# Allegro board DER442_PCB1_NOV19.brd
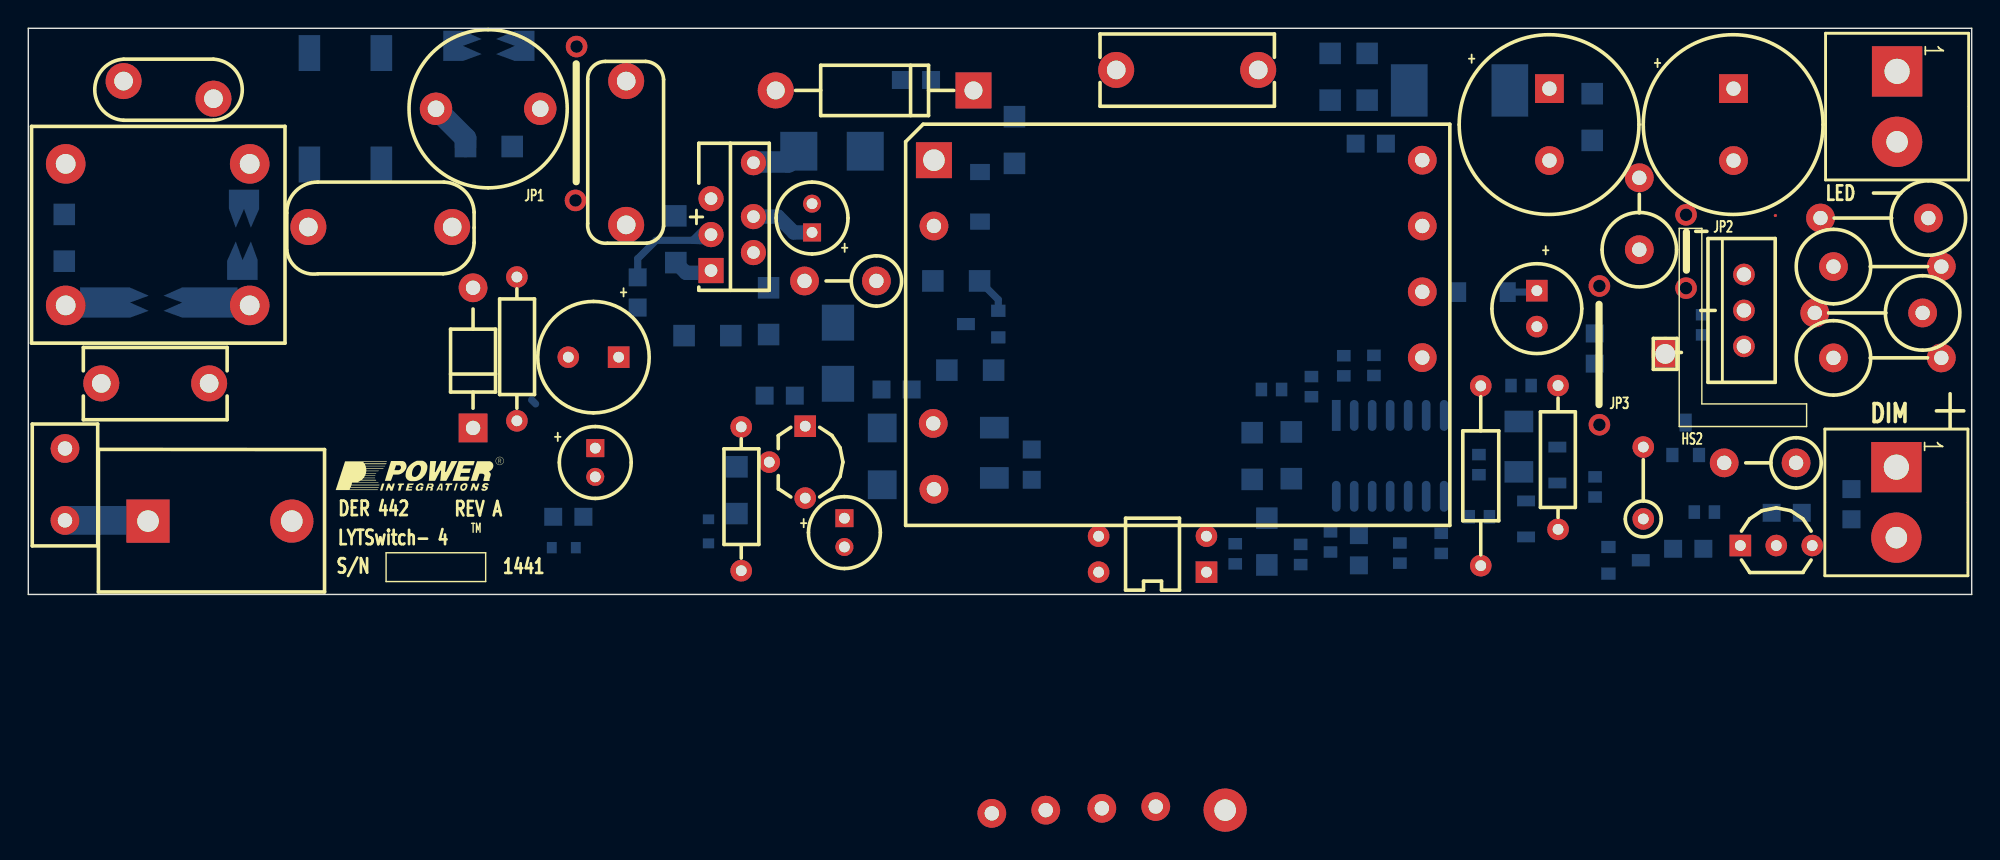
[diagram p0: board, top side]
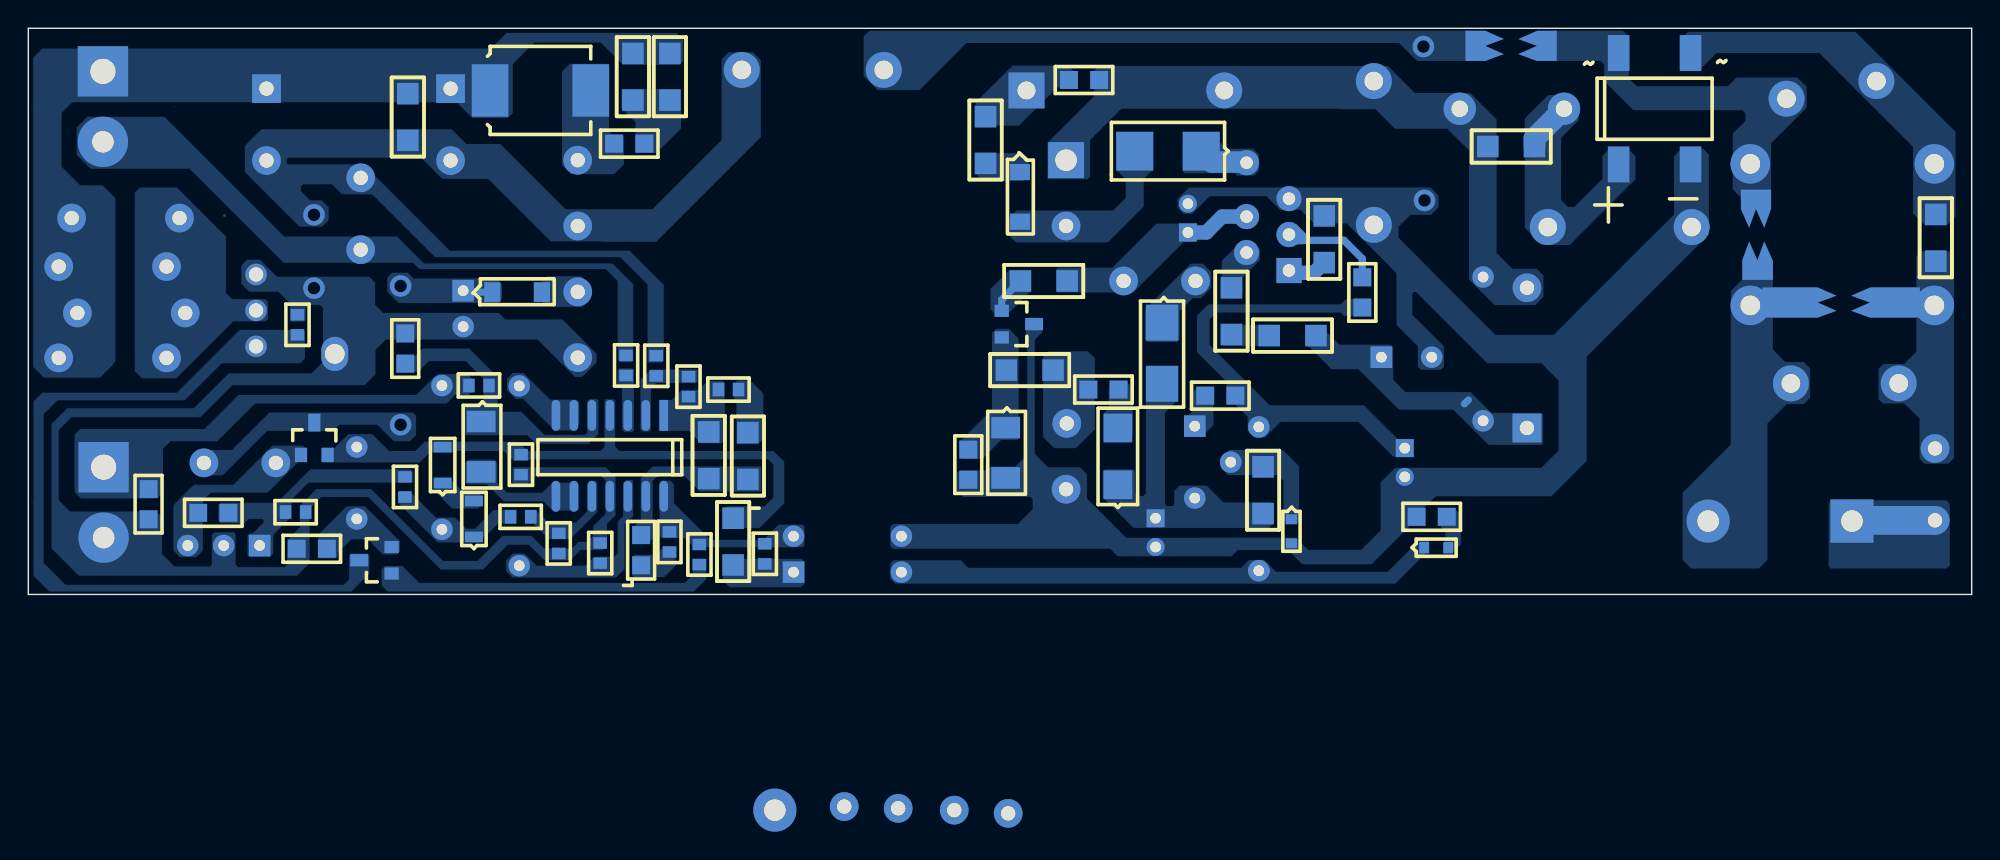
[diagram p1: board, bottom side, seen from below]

Outline 137.3 x 40 mm; copper layers: TOP, BOTTOM. Coordinates in mm from the lower left corner of the outline.
Outline path: 0,40 0,0 137.3,0 137.3,40 0,40

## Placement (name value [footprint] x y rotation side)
BR1  DF08S  [PISMDDFS]  24.94 30.43 0 bottom
C1  47 nF  [PI_NP395X200LS300D040]  5.16 14.91 0 top
C2  100 nF  [PINPCAPRAD500X260400040]  29.97 25.98 180 top
C3  220 nF  [PI_NP_CAP_RAD470X220LS400D40]  42.24 36.27 270 top
C4  4.7 uF  [PIPOLCAPCLYD320LS140030]  39.93 16.76 180 top
C5  1 nF  [PISMC0805]  61.65 36.35 0 bottom
C6  4.7 uF  [PIPOLCAPCLYD200LS80030]  55.37 25.58 90 top
C7  10 uF  [PIPOLCAPCLYD200LS80030]  40.06 10.34 270 top
C8  10 uF  [PIPOLCAPCLYD200LS80030]  57.66 5.38 270 top
C9  2.2nF  [PI_NP475X200LS395D040]  76.86 37.06 0 top
C15  1 uF  [PISMC0805]  125.3 5.77 180 bottom
C16  100 nF  [PISMC0603]  102.49 9.88 270 bottom
C17  10 uF  [PISMC0805]  94.01 2.06 90 bottom
C18  1 nF  [PISMC0805]  110.67 16.31 90 bottom
C21  100 uF  [PIPOLCAPCYLD250LS100030]  106.58 21.46 270 top
C24  330 uF  [PIPOLCAPCLYD500LS200040]  120.47 35.74 270 top
C25  330 uF  [PIPOLCAPCLYD500LS200040]  107.47 35.74 270 top
C26  Option  [PISMC1206]  86.46 11.43 270 bottom
C27  100 pF  [PISMC0805]  95.91 31.85 180 bottom
C28  10 uF  [PISMC0805]  128.8 5.31 90 bottom
D5  1N4007  [PIDV200X110X040DO41]  31.42 11.76 90 top
D6  UFM15PL-TP  [PI_SM_SOD-123_12]  67.23 29.84 270 bottom
D7  ES2D  [PISMDO214AA12]  54.43 31.32 0 bottom
D8  ES1B-13-F  [PISMDO214AC12]  57.2 19.2 270 bottom
D9  US1D  [PISMDSMA]  60.33 7.75 90 bottom
D10  DL4148  [PISMDMINIMELF]  68.25 11.79 270 bottom
D13  DL4148  [PISMDMINIMELF]  105.31 12.22 270 bottom
D16  ES3G-E3/57T  [PISMDO214AB12]  104.67 35.61 180 bottom
D17  DA22F2100L  [PI_SM_SOD-123_12]  104.52 21.36 180 bottom
D18  BAV16WS-7-F  [PISMSOD323]  108.03 7.87 90 bottom
D19  BAV16WS-7-F  [PISMSOD323]  105.82 4.06 90 bottom
F1  3.15 A  [PI_RST_MICROFUSE]  2.59 5.23 90 top
HS_POST1  Option  [PI_HSK_POST]  115.65 16.99 90 top
J1  TERMINAL BLOCK  [PI_TERM_BLOCK_3PIN]  8.46 5.18 270 top
J2  CON1  [PI_HDR_2PIN_PHOENIX_196LS]  132.03 36.96 270 top
J3  CON2  [PI_HDR_2PIN_PHOENIX_196LS]  131.98 8.99 270 top
L1  8.8 mH  [PIIND4P710X590LS512X055]  2.64 20.42 90 top
L4  1.5 mh  [PI_CHOKE_710HX450LS290D046]  28.8 34.32 0 top
NOREF  -  []  -168.95 52.63 0 top
NOREF#2  -  []  -246.76 -146.38 0 top
NOREF#3  -  []  0 40 0 top
NOREF#4  -  []  21.72 7.32 0 top
NOREF#5  -  []  0 0 90 top
Q1  2N5551  [PITO92R100]  54.89 11.89 270 top
Q2  MMBT3904  [PISMSOT23132]  116.15 9.86 180 bottom
Q5  MMBT3906  [PISMSOT23132]  111.63 3.35 90 bottom
Q6  2SC4883  [PI_TO220F]  121.21 17.53 90 top
R1  75 k  [PISMR1206]  2.54 23.55 90 bottom
R4  1 M  [PISMR1206]  46.33 18.29 0 bottom
R5  825 k  [PISMR1206]  52.3 18.36 90 bottom
R6  680 k  [PI14WVRESD100LS100D030#2]  34.52 22.43 270 top
R9  75  [PISMR1206]  69.67 33.76 270 bottom
R10  24.9 k  [PISMR1206]  45.75 23.44 90 bottom
R11  4.7 k  [PI1WRESD200LS725D040]  59.92 22.15 180 top
R12  7.5 k  [PISMR0805]  54.15 14.05 180 bottom
R13  8.2 k  [PISMR0805]  43.05 20.27 90 bottom
R17  5.1 k  [PISMR1206]  50.06 5.71 90 bottom
R18  3.3 k  [PI14WVRESD100LS100D030#2]  50.37 11.84 270 top
R19  20  [PISMR1206]  63.91 22.15 0 bottom
R20  1.74 k  [PISMR0805]  37.08 5.49 0 bottom
R21  78.7 k  [PISMR1206]  64.9 15.85 0 bottom
R22  5.49 k  [PISMR0805]  70.89 10.24 270 bottom
R25  4.32 k  [PISMR0603]  92.94 15.44 90 bottom
R26  4.32 k  [PISMR0603]  95.07 15.47 90 bottom
R28  88.7 k  [PISMR0603]  90.65 15.39 270 bottom
R29  1 k  [PI1WRESD200LS725D040]  124.89 9.3 180 top
R31  30.9 k  [PISMR0603]  110.69 6.88 90 bottom
R32  10 k  [PISMR0603]  119.13 5.82 180 bottom
R33  3.01 k  [PISMR1206]  87.5 5.38 270 bottom
R34  3.65 k  [PISMR0603]  92 4.42 270 bottom
R35  4.7 k  [PISMR1206]  89.23 8.18 90 bottom
R36  24 k  [PI14WVRESD100LS100D030#3]  102.62 14.73 270 top
R37  9.09 k  [PISMR0603]  96.9 2.21 90 bottom
R38  88.7 k  [PISMR0603]  103.23 5.49 180 bottom
R39  14.7 k  [PISMR0603]  99.82 4.32 270 bottom
R40  20 k  [PI14WVRESD100LS100D030#2]  108.08 4.6 90 top
R41  10 k  [PISMR0603]  104.75 14.76 0 bottom
R45  Option  [PISMR1206]  30.89 31.65 0 bottom
R46  0.25  [PI1WRESD200LS500D040]  113.82 24.36 90 top
R49  2 k  [PI14WVRESD100LS100D030]  114.1 5.33 90 top
R51  1.1 k  [PI2WRESD200LS725D040]  134.24 26.59 180 top
R56  1 k  [PISMR0603]  89.89 2.11 90 bottom
R58  1.1 k  [PI2WRESD200LS725D040]  133.83 19.89 180 top
R59  1.1 k  [PI2WRESD200LS725D040]  127.53 23.16 0 top
R60  1.1 k  [PI2WRESD200LS725D040]  127.53 16.71 0 top
R61  750  [PISMR0805]  118.34 3.23 180 bottom
R62  Option  [PISMR0603]  88.54 14.48 180 bottom
R66  Option  [PISMR0603]  85.27 2.16 90 bottom
R67  Option  [PISMR0603]  118.29 18.34 90 bottom
R68  20.0  [PISMR0805]  60.27 14.48 0 bottom
R69  392 k  [PISMR1206]  110.49 35.38 270 bottom
R70  82  [PISMR1206]  91.97 34.92 90 bottom
R71  82  [PISMR1206]  94.59 34.92 90 bottom
RV1  140 Vac  [PINPCAPRAD370X156250040]  6.73 36.3 0 top
T1  EF25  [PI_BOBBIN_EF25_H_12P]  63.98 30.68 0 top
U1  LYT4315E  [PIICESIP76TH]  48.23 22.89 90 top
U2  LM431AIM3  [PISMSOT23123]  68.53 18.16 270 bottom
U3  SFH615A--3  [PI_DIP4]  83.24 1.57 90 top
U5  LM431_A  [PI_TL431CLP]  120.95 3.45 0 top
U6  LM324M  [PISOG05014WB300L400]  92.41 12.65 0 bottom
VR1  P6KE150A  [PIDV200X140X050DO15DO204AC]  66.78 35.61 180 top
VR2  DZ2S08200L  [PI_SM_D_SSMINI2P]  48.06 5.31 270 bottom
VR3  DZ2S03900L  [PI_SM_D_SSMINI2P]  38.68 3.3 180 bottom

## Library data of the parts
BR1 = DIODE BRIDGE_+-~~
C1 C3 C9 C15-C18 C26-C28 = CAP NP
C2 = CAP NP: alternate symbols: (pinpcaprad500x260400040h)
C4 = CAP POL: alternate symbols: (pipolcapclyd320ls140030h); tolerance: 20
C5 = CAP NP: tolerance: 10
C6 = CAP POL: alternate symbols: (pipolcapclyd200ls80030h)
C7 = CAP POL
C8 = CAP POL: tolerance: 20
C21 = CAP POL: alternate symbols: (pipolcapcyld250ls100030h)
C24 C25 = CAP POL: alternate symbols: (pipolcapclyd500ls2000401000lh)
D5 = DIODE: alternate symbols: (pidax475x125040do41,pidv200x110x040do41wbead,pidax390x125040do41)
D6-D10 D13 D16-D19 = DIODE
F1 = FUSE
HS_POST1 = HS_POST
J1 = CON3
J2 J3 = CON2
L1 = INDUCTOR_4P_NP
L4 = INDUCTOR: tolerance: 0.1
Q1 = NPN_EBC: alternate symbols: (PIT092100)
Q2 = NPN_BEC
Q5 = PNP_BEC
Q6 = NPN_BCE: alternate symbols: (pi_to220F_vf1)
R1 R4 R5 R9 R10 R12 R13 R17 R20 R22 R28 R31-R34 R37-R39 R41 R56 R61 R62 R66-R71 = R
R6 R18 R36 R40 R49 = R: alternate symbols: (pi14wvresd100ls200d030,pi14wresd100ls400d030,pi14wresd100ls500d030)
R11 R29 = R: alternate symbols: (pi1wvresd120ls200d040,pi1wvresd120ls300d040,pi1wvresd200ls200d040,pi1wvresd200ls300d040,pi1wvresd200ls350d040)
R19 R21 R25 R26 R35 R45 = R: tolerance: 5%
R46 = R: alternate symbols: (pi1wvresd200ls200d040)
R51 R58-R60 = R: alternate symbols: (pi2wresd200ls900d040,pi2wvresd200ls300d040,pi2wvresd200ls400d040)
RV1 = VARISTOR
T1 = BEI30_12P/GENERIC
U1 = LNK40X_eSIP
U2 = TL431/SOT-23_CAR
U3 = OPTO_A_B
U5 = KA431A/TO92: tolerance: 1%
U6 = LM324
VR1 = DIODE_ZENER: alternate symbols: (pidax550x140050do15do204ac)
VR2 VR3 = DIODE_ZENER

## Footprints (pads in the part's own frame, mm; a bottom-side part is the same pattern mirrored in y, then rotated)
PI1WRESD200LS500D040
  round 2.032 hole 1.016: 1(0,0) 2(5.08,0)
PI1WRESD200LS725D040
  round 2.032 hole 1.016: 1(0,0) 2(5.08,0)
PI2WRESD200LS725D040
  round 2.032 hole 1.016: 1(0,0) 2(7.62,0)
PI14WVRESD100LS100D030
  round 1.524 hole 0.762: 1(0,0) 2(5.08,0)
PI14WVRESD100LS100D030#2
  round 1.524 hole 0.762: 1(0,0) 2(10.16,0)
PI14WVRESD100LS100D030#3
  round 1.524 hole 0.762: 1(0,0) 2(12.7,0)
PI_BOBBIN_EF25_H_12P
  rect 2.54x2.54 hole 1.524: 1(0,0)
  round 2.032 hole 1.016: 2(0,-4.651) 3(4.089,-46.152) 4(7.899,-45.923) 5(-0.051,-18.6) 6(0,-23.251) 7(11.862,-45.796) 8(15.672,-45.669) 9(34.501,-13.95) 10(34.501,-9.302) 11(34.501,-4.651) 12(34.501,0)
PI_CHOKE_710HX450LS290D046
  round 2.286 hole 1.168: 1(0,0) 2(7.366,0)
PI_DIP4
  rect 1.524x1.524 hole 0.762: 1(0,0)
  round 1.524 hole 0.762: 2(2.54,0) 3(2.54,7.62) 4(0,7.62)
PI_HDR_2PIN_PHOENIX_196LS
  rect 3.556x3.556 hole 1.778: 1(0,0)
  round 3.556 hole 1.524: 2(4.978,0)
PI_HSK_POST
  oval 2.413x1.905 hole 1.397: 1(0,0)
PI_NP395X200LS300D040
  round 2.54 hole 1.321: 1(0,0) 2(7.62,0)
PI_NP475X200LS395D040
  round 2.54 hole 1.321: 1(0,0) 2(10.033,0)
PI_NP_CAP_RAD470X220LS400D40
  round 2.54 hole 1.321: 1(0,0) 2(10.16,0)
PI_RST_MICROFUSE
  round 2.032 hole 1.016: 1(0,0) 2(5.08,0)
PI_SM_D_SSMINI2P
  rect 0.699x0.8 smd: 1(0,0) 2(1.699,0)
PI_SM_SOD-123_12
  rect 1.143x1.397 smd: 1(0,0) 2(3.505,0)
PI_TERM_BLOCK_3PIN
  rect 3.048x3.048 hole 1.524: 1(0,0)
  round 3.048 hole 1.524: 2(20.422,76.098) 3(0,10.16)
PI_TL431CLP
  rect 1.524x1.524 hole 0.762: 1(0,0)
  round 1.524 hole 0.762: 2(2.54,0) 3(5.08,0)
PI_TO220F
  round 1.524 hole 1.016: 1(0,0) 2(2.54,0) 3(5.08,0)
PIDV200X110X040DO41
  rect 2.032x2.032 hole 1.016: 1(0,0)
  round 2.032 hole 1.016: 2(9.906,0)
PIDV200X140X050DO15DO204AC
  rect 2.54x2.54 hole 1.27: 1(0,0)
  round 2.54 hole 1.27: 2(13.97,0)
PIICESIP76TH
  rect 1.778x1.778 hole 0.889: 1(0,0)
  round 1.778 hole 0.889: 2(1.27,-2.997) 3(2.54,0) 4(3.81,-2.997) 5(5.08,0) 7(7.62,-2.997)
PIIND4P710X590LS512X055
  round 2.794 hole 1.397: 1(10,-13) 2(0,-13) 3(0,0) 4(10,0)
PINPCAPRAD370X156250040
  round 2.54 hole 1.321: 1(0,-0.025) 2(6.35,-1.27)
PINPCAPRAD500X260400040
  round 2.54 hole 1.321: 1(0.025,0.025) 2(10.185,0.025)
PIPOLCAPCLYD200LS80030
  rect 1.27x1.27 hole 0.762: 1(0,0)
  round 1.27 hole 0.762: 2(2.032,0)
PIPOLCAPCLYD320LS140030
  rect 1.524x1.524 hole 0.762: 1(-1.778,0)
  round 1.524 hole 0.762: 2(1.778,0)
PIPOLCAPCLYD500LS200040
  rect 2.032x2.032 hole 1.016: 1(0,0)
  round 2.032 hole 1.016: 2(5.08,0)
PIPOLCAPCYLD250LS100030
  rect 1.524x1.524 hole 0.762: 1(0,0)
  round 1.524 hole 0.762: 2(2.54,0)
PISMC0603
  rect 0.813x0.965 smd: 1(0,0) 2(1.422,0)
PISMC0805
  rect 1.27x1.27 smd: 1(0,0) 2(2.134,0)
PISMC1206
  rect 1.524x1.524 smd: 1(0,0) 2(3.302,0)
PISMDDFS
  rect 1.524x2.54 smd: 1(0,0.051) 2(-5.08,0.051) 3(0,-7.823) 4(-5.08,-7.823)
PISMDMINIMELF
  rect 1.524x2.032 smd: 1(0,0) 2(3.556,0)
PISMDO214AA12
  rect 2.616x2.743 smd: 1(0,0) 2(4.699,0)
PISMDO214AB12
  rect 2.591x3.708 smd: 1(0,0) 2(7.112,0)
PISMDO214AC12
  rect 2.54x2.286 smd: 1(0,0) 2(4.318,0)
PISMDSMA
  rect 2.032x2.032 smd: 1(0,0) 2(4.013,0)
PISMR0603
  rect 0.813x0.965 smd: 1(0,0) 2(1.422,0)
PISMR0805
  rect 1.27x1.27 smd: 1(0,0) 2(2.134,0)
PISMR1206
  rect 1.524x1.524 smd: 1(0,0) 2(3.302,0)
PISMSOD323
  rect 0.762x1.27 smd: 1(0,0) 2(2.54,0)
PISMSOT23123
  rect 0.864x1.016 smd: 1(-1.88,0) 3(0,0)
  rect 0.864x1.27 smd: 2(-0.94,2.286)
PISMSOT23132
  rect 0.864x1.016 smd: 1(-1.88,0) 2(0,0)
  rect 0.864x1.27 smd: 3(-0.94,2.286)
PISOG05014WB300L400
  rect 0.61x2.184 smd: 1(0,0)
  oval 0.61x2.184 smd: 2(1.27,0) 3(2.54,0) 4(3.81,0) 5(5.08,0) 6(6.35,0) 7(7.62,0) 8(7.62,5.715) 9(6.35,5.715) 10(5.08,5.715) 11(3.81,5.715) 12(2.54,5.715) 13(1.27,5.715) 14(0,5.715)
PITO92R100
  rect 1.524x1.524 hole 0.762: 1(0,0)
  round 1.524 hole 0.762: 2(2.54,-2.54) 3(5.08,0)

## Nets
N3036325: C3.1 C5.1 D5.2 L4.2 R6.1 R45.2 T1.1 VR1.2
N3036377: C7.1 R12.2 R13.1 R18.1
N3036609: C24.1 C25.1 D16.1 J2.1 R51.1 R58.1 R59.2 R60.2 R69.1 R70.2 R71.2
N3036925: R4.2 R5.1
N3037005: D7.1 U1.7(D)
N3037093: D6.2 D7.2 T1.2
N3037213: C4.1 D5.1 R4.1 R6.2
N3037237: BR1.2 C2.2 C3.2 C4.2 C6.2 C7.2 C8.2 C9.1 D10.2 R10.2 R20.2 R22.2 T1.6 U1.5(S) U2.2(A) U3.3(E) VR2.2
N3037245: C6.1 R11.1 R19.1 U1.4(BP)
N3037491: BR1.3 L1.1 RV1.2
N3037573: R10.1 U1.1(R)
N3037677: C9.2 C16.2 C18.2 C21.2 C24.2 C25.2 C28.1 HS_POST1.1 J3.2 Q6.3(EMITTER) R25.2 R32.2 R37.2 R39.2 R46.2 R61.1 R67.2 R69.2 T1.9 T1.11 U5.2(A) U6.11(V-)
N3037713: R33.2 R66.1 U3.1(A)
N3038127: R18.2 U3.4(C) VR3.1
N3038179: C15.1 Q2.1(BASE) R29.2 U5.3(C)
N3038231: R5.2 U1.2(V)
N3038285: C21.1 D17.1 Q2.3(COLLECTOR) R29.1
N3038435: D8.1 R11.2
N3038533: F1.1 J1.1
N3038609: Q1.1(EMITTER) R12.1
N3038711: BR1.4 L1.4 R1.2 RV1.1
N3039958: BR1.1 C2.1 L4.1 R45.1
N3046185: D6.1 R9.2
N3047792: C8.1 D8.2 D9.1 Q1.3(COLLECTOR) R17.1
N3060476: R19.2 U2.1(C)
N3061243: D10.1 R21.2 R22.1 U2.3(VREF)
N3061835: R21.1 R68.2 T1.5
N3064352: C27.1 D16.2 T1.12
N3067766: J2.2 R26.2 R46.1
N3070784: R25.1 R28.1 U6.2(IN-)
N3070798: R28.2 R35.2 R62.1 U6.1(OUT)
N3070937: R34.1 R56.2 R66.2 U3.2(C) U6.14(OUT)
N3070979: C16.1 D18.2 Q2.2(EMITTER) R33.1 R49.2 U6.4(V+)
N3073888: D19.1 R31.1 R38.1 R40.1
N3073903: C15.2 R31.2 R32.1 U5.1(VREF)
N3074477: C17.1 R34.2
N3074493: R36.1 U6.6(IN-) U6.7(OUT)
N3074930: R36.2 R37.1 U6.12(IN+)
N3075106: C17.2 C26.2 R35.1 U6.13(IN-)
N3077075: C28.2 J3.1 R40.2 R41.2
N3077081: C18.1 D13.1 R41.1 U6.5(IN+)
N3083007: D13.2 U6.8(OUT) U6.9(IN-)
N3083089: R38.2 R39.1 U6.10(IN+)
N3109029: C1.1 F1.2 L1.3 R1.1
N3109086: C1.2 J1.3 L1.2
N3119295: C5.2 R9.1 VR1.1
N3151365: D17.2 T1.10
N3165324: R13.2 U1.3(FB)
N3168759: Q1.2(BASE) R17.2 VR2.1
N3178422: R26.1 U6.3(IN+)
N3201252: Q5.2(EMITTER) R49.1 R61.2
N3203116: Q6.2(COLLECTOR) R51.2 R58.2 R59.1 R60.1
N3205512: Q5.3(COLLECTOR) Q6.1(BASE) R67.1
N3220537: C26.1 R62.2
N3225688: D18.1 D19.2
N3249281: D9.2 R68.1
N3253476: Q5.1(BASE) R56.1
N3273823: R20.1 VR3.2
N3286857: C27.2 R70.1 R71.1

Pads without a net: J1 2; T1 3 4 7 8

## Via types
v1: diameter 1.524, hole 0.889, TOP to BOTTOM, 6 vias

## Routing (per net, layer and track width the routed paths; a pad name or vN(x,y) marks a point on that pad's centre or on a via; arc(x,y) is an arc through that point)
N3036325: length 0.5
  BOTTOM w0.508: 42.24,35.81 C3.1
N3036377: length 0.1
  BOTTOM w0.508: 43.13,20.19 R13.1
N3037005: length 3.4
  BOTTOM w1.524: 51.36,30.56 53.67,30.56 D7.1
N3037213: length 0.4
  BOTTOM w0.508: 35.56,13.74 35.84,13.46
N3037237: length 0.9
  BOTTOM w0.762: 38.73,38.84 v1(38.73,38.71) 38.71,38.71
  BOTTOM w1.016: 64.33,7.43 T1.6 63.98,7.34 ; 48.16,28.02 48.21,27.97
  BOTTOM w1.27: 48.36,28.02 48.16,28.02
  vias: v1(38.66,27.84)
N3037245: length 4.6
  BOTTOM w1.016: U1.4 52.96,26.7 54.08,25.58 C6.1
N3037573: length 2.9
  BOTTOM w1.016: U1.1 48.08,22.73 46.46,22.73 R10.1
N3037677: length 0.8
  BOTTOM w1.016: 107.34,30.53 C25.2
  BOTTOM w1.27: 98.48,26.36 T1.11
  BOTTOM w1.524: C25.2 107.47,30.4
  vias: v1(117.12,26.82) v1(117.12,21.64)
N3038127: length 0.9
  BOTTOM w0.508: 50.42,1.75 50.88,1.75
  BOTTOM w0.762: R18.2 49.96,1.68
N3038285: length 2.1
  BOTTOM w0.508: C21.1 106.48,21.36 D17.1
  vias: v1(111,21.79) v1(111,11.99)
N3038533: length 5.9
  BOTTOM w2.032: J1.1 8.41,5.23 F1.1
N3039958: length 3.5
  BOTTOM w1.524: R45.1 30.89,32.23 L4.1
N3060476: length 2.7
  BOTTOM w0.508: R19.2 68.53,20.83 U2.1
N3165324: length 7.2
  BOTTOM w0.508: R13.2 43.05,23.72 44.35,25.02 47.83,25.02 U1.3
N3203116: length 0.5
  BOTTOM w0.762: 121.39,19.89 Q6.2
  BOTTOM w1.016: 126.03,20.07 R58.2

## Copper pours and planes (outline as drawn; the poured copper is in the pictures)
N3036325 on BOTTOM: 33.57,24.13 33.57,33.57 35.43,35.43 39.34,35.43 41.25,37.34 61.67,37.34 62,37.01 62,35.2 65.3,31.9 65.3,29.34 62.46,29.34 62.28,29.51 62.28,32.11 60.07,34.32 44.73,34.32 44.7,34.29 42.14,34.29 40.75,32.91 37.05,32.91 35.51,31.37 35.51,22.25 33.71,20.45 30.84,20.45 30.25,21.03 30.25,22.53 30.73,23.01 32.45,23.01
N3036377 on BOTTOM: 49.58,13.36 53.85,17.63 53.85,19.43 53.37,19.91 44.58,19.91 44.35,19.68 42.65,19.68 42.44,19.89 42.44,20.68 42.63,20.87 44.21,20.87 44.58,20.5 53.94,20.5 54.73,19.7 54.73,17.11 52.65,15.04 52.65,14.05 51.16,12.55 51.16,11.58 50.65,11.07 49.94,11.07 48.82,12.19 43.33,12.19 40.88,9.74 39.48,9.74 39.47,9.73 39.47,10.85 39.5,10.87 40.44,10.87 42.93,13.36
N3036609 on BOTTOM: 132.23,15.32 131.29,16.26 131.29,16.31 131.14,16.46 131.14,27.99 132.05,28.9 133.63,28.9 134.95,30.23 134.95,34.01 134.19,34.77 107.04,34.77 105.93,33.67 103.42,33.67 103.07,34.01 103.07,37.47 101.55,38.99 96.85,38.99 95.28,37.41 91.31,37.41 91.03,37.69 91.03,39.22 91.49,39.67 103.5,39.67 104.61,38.57 136.31,38.57 136.96,37.92 136.96,16.08 136.19,15.32
N3036925 on BOTTOM: 53.04,17.75 52.83,17.55 49.05,17.55 48.87,17.73 48.87,18.92 49,19.05 52.96,19.05 53.04,18.97
N3037005 on BOTTOM: 55.73,32.08 55.73,29.87 55.61,29.76 52.06,29.76 51.89,29.59 50.7,29.59 50.37,29.92 50.37,31.09 50.77,31.5 52.65,31.5 53.14,31.98 53.14,32.23 53.26,32.36 55.45,32.36
N3037093 on BOTTOM: 58.5,27.41 58.5,29.36 58.01,29.84 57.99,29.84 57.86,29.97 57.86,32.11 58.19,32.44 60.02,32.44 60.38,32.08 60.38,29.95 59.77,29.34 59.77,29.24 59.79,29.21 59.77,29.21 59.77,28.02 60.66,27.13 67.49,27.13 68.02,26.59 68.02,25.37 67.51,24.87 61.04,24.87
N3037213 on BOTTOM: 33.93,12.83 35.41,14.3 40.01,14.3 40.87,15.16 40.87,17.48 41.05,17.65 44.68,17.65 45.87,18.85 46.91,18.85 47.07,18.69 47.07,17.7 47.02,17.7 45.22,15.91 43.32,15.91 40.46,13.06 36.63,13.06 34.12,10.55 34.11,10.57 30.38,10.57 30.28,10.67 30.28,12.7 30.4,12.83
N3037237 on BOTTOM (solid shape): 35.76,37.69 34.37,37.69 33.05,38.18 34.37,38.76 33.05,39.24 34.37,39.83 35.76,39.83
N3037237 on BOTTOM: outline of 100 points within 18.57,2.13 76.4,31.47
N3037237 on BOTTOM: 35.74,39.83 77.88,39.83 78.28,39.42 78.28,36.63 77.29,35.64 74.35,35.64 71.02,38.96 40.46,38.96 39.19,37.69 35.51,37.69 35.51,39.6
N3037245 on BOTTOM: 60.71,23.09 64.54,23.09 64.69,22.94 64.69,21.44 64.59,21.34 59.23,21.34 55.68,24.89 54.86,24.89 54.79,24.97 54.79,26.19 54.8,26.2 57.59,26.2
N3037491 on BOTTOM (solid shape): 16.31,27.23 15.72,25.91 15.24,27.23 14.66,25.91 14.17,27.25 14.17,28.6 16.31,28.6
N3037491 on BOTTOM (solid shape): 32.03,39.24 30.71,38.76 32.03,38.18 30.71,37.69 29.31,37.69 29.31,39.83 30.68,39.83
N3037491 on BOTTOM: 24.64,39.83 24.23,39.42 24.23,36.47 23.66,35.9 17.23,35.9 16.61,36.53 12.32,36.53 11.66,35.86 11.66,34.39 14.17,31.88 14.17,28.17 14.25,28.09 16.36,28.09 16.88,28.61 16.88,32.56 15.99,33.45 15.99,34 16.21,34.21 23.9,34.21 25.96,36.27 25.96,37.44 26.21,37.69 29.64,37.69 29.64,39.83
N3037677 on BOTTOM: outline of 106 points within 95.81,1.32 135.66,23.65
N3037677 on BOTTOM: 92.56,16.38 92.41,16.54 92.41,21.87 94.82,24.28 107.52,24.28 113.63,30.39 118.96,30.39 119.05,30.48 119.05,30.76 118.95,30.86 109.55,30.86 108.05,29.36 104.8,29.36 100.38,24.94 96.72,24.94 96.75,24.92 92.94,24.92 85.55,32.31 85.55,37.74 86.11,38.3 87.83,38.3 88.32,37.82 88.32,32.11 93.21,27.22 99.34,27.22 103.95,31.83 106.35,31.83 107.39,32.87 120.83,32.87 122,31.7 122,29.84 118.14,25.98 116.54,25.98 116.08,26.44 116.08,27.36 116.56,27.84 117.37,27.84 118.03,28.5 118.03,28.83 117.88,28.98 115.85,28.98 115.14,28.27 113,28.27 108.56,23.83 95.48,23.83 93.55,21.89 93.55,16.38
N3037713 on BOTTOM: 82.68,2.51 88.09,2.51 88.11,2.54 88.24,2.41 88.24,0.99 87.76,0.51 82.73,0.51 82.46,0.77 82.46,2.3
N3038127 on BOTTOM: 40.72,0.76 38.33,3.15 38.33,3.76 38.43,3.86 38.99,3.86 41.25,1.6 49.15,1.6 49.99,2.44 51.05,2.44 51.61,1.88 70.89,1.88 71.42,2.41 76.17,2.41 76.4,2.18 76.4,1.12 76.05,0.76
N3038179 on BOTTOM: 117.91,10.52 120.04,10.52 122.81,7.75 125.6,7.75 127.05,6.3 127.05,3.1 126.59,2.64 125.43,2.64 124.97,3.1 124.97,6.63 124.41,7.19 120.4,7.19 118.19,9.4 117.68,9.4 117.68,10.29
N3038231 on BOTTOM: 52.98,23.57 52.98,21.26 52.73,21.01 51.92,21.01 51.51,21.41 51.51,22.4 50.29,23.62 50.29,24.36 50.83,24.89 51.66,24.89
N3038285 on BOTTOM: 104.27,22.33 110.08,22.33 110.49,22.73 111.61,22.73 111.94,22.4 111.94,21.39 111.14,20.59 104.13,20.59 103.84,20.88 103.84,21.89
N3038285 on BOTTOM: 120.27,12.85 122.91,10.21 125.35,10.21 125.78,9.78 125.78,8.84 125.35,8.41 123.57,8.41 120.42,11.56 115.77,11.56 115.34,11.99 112.65,11.99 111.48,10.82 110.34,10.82 109.91,11.25 109.91,12.62 110.13,12.85
N3038435 on BOTTOM: 55.04,20.93 54.46,20.93 53.72,21.67 53.72,22.78 54.31,23.37 55.17,23.37 58.42,20.12 58.42,18.03 58.22,17.83 56.13,17.83 55.96,18.01 55.96,20.02
N3038533 on BOTTOM: 10.11,6.43 10.11,1.98 9.96,1.83 1.78,1.83 1.55,2.06 1.55,6.4 1.8,6.65 9.88,6.65
N3038609 on BOTTOM: 54.99,14.33 54.99,13 55.63,12.37 55.63,11.33 55.45,11.15 54.38,11.15 53.57,11.96 53.57,14.4 53.72,14.55 54.76,14.55
N3038711 on BOTTOM: 1.68,26.14 3.35,26.14 4.14,26.92 4.14,31.62 10.77,38.25 18.03,38.25 19.28,37.01 20.37,37.01 20.62,37.26 20.62,39.17 20.04,39.75 8.2,39.75 1.14,32.69 1.14,26.67
N3039958 on BOTTOM: 29.92,35.28 31.57,33.63 31.57,25.91 30.35,24.69 28.4,24.69 23.75,29.34 23.75,30.99 23.77,30.99 24.28,31.5 25.58,31.5 26.09,30.99 26.09,29.36 28.07,27.38 28.52,27.38 29.01,27.86 29.01,32.26 27.76,33.5 27.76,34.75 28.3,35.28
N3046185 on BOTTOM: 66.62,30.78 67.02,31.18 68.44,31.18 68.45,31.17 70.21,31.17 70.41,30.96 70.41,29.77 69.85,29.21 67.03,29.21 66.62,29.62
N3047792 on BOTTOM: 54.05,7.7 55.96,7.7 56.34,7.32 56.34,6.38 56.46,6.25 56.87,6.25 57,6.38 57,12.83 56.1,13.73 56.11,13.74 56.11,15.77 56.36,16.03 58.06,16.03 58.34,15.75 58.34,7.14 58.52,6.96 58.9,6.96 59.11,7.16 59.11,8.69 59.26,8.84 61.21,8.84 61.39,8.66 61.39,6.88 59.21,4.7 49.66,4.7 49.31,5.04 49.31,6.22 49.59,6.5 52.86,6.5
N3060476 on BOTTOM: 69.32,20.14 68.94,19.76 68.94,19.74 68.17,19.74 66.47,21.44 66.47,22.61 66.7,22.83 68.07,22.83 69.32,21.59
N3061243 on BOTTOM: 68.02,18.77 68.91,18.77 69.22,18.47 69.22,13.08 71.5,10.79 71.5,9.75 71.32,9.58 69.9,9.58 68.55,10.92 67.41,10.92 67.34,11 67.34,18.08
N3061835 on BOTTOM: 61.95,16.69 62.45,17.18 65.23,17.18 65.61,16.8 65.61,11.13 64.82,10.34 63.27,10.34 61.95,11.66
N3064352 on BOTTOM: 99.06,37.49 99.59,36.96 99.59,30.35 98.93,29.69 95.91,29.69 95.22,30.38 95.22,32.31 95.45,32.54 96.06,32.54 96.27,32.74 96.27,37.26 96.49,37.49
N3067766 on BOTTOM: 94.69,16.41 94.56,16.54 94.56,21.92 96.04,23.39 109.35,23.39 111.24,25.29 119.19,25.29 119.2,25.27 127.67,33.74 133.13,33.74 133.88,32.99 133.88,31.06 132.89,30.07 125.91,30.07 119.27,23.43 110.11,23.43 109.66,22.99 96.49,22.99 96.28,22.77 96.28,22.76 95.66,22.14 95.66,16.59 95.48,16.41
N3070784 on BOTTOM: 90.09,15.9 93.32,15.9 94.06,15.16 94.06,11.61 93.95,11.51 93.4,11.51 93.32,11.58 93.32,14.55 92.94,14.94 90.12,14.94 90.02,15.04 90.02,15.82
N3070798 on BOTTOM: 88.24,15.09 89.31,15.09 89.94,14.45 91.14,14.45 91.85,13.74 92.68,13.74 92.71,13.77 92.76,13.72 92.76,11.56 90.65,11.56 89.76,10.67 88.34,10.67 88.09,10.92 88.09,14.94
N3070937 on BOTTOM: 84.3,4.93 85.37,3.86 89.1,3.86 91.69,6.45 91.69,7.8 91.94,8.04 92.57,8.04 92.71,7.9 92.71,4.14 92.56,3.99 90.96,3.99 90.3,3.33 82.83,3.33 82.82,3.34 82.59,3.34 82.46,3.47 82.46,4.79 82.6,4.93
N3070979 on BOTTOM: 85.62,4.7 83.9,6.43 83.9,9.37 84.66,10.13 95.53,10.13 95.83,10.44 95.83,13.74 95.89,13.79 96.55,13.79 96.6,13.74 96.6,10.41 96.88,10.13 102.03,10.13 102.69,10.79 109.3,10.79 109.96,10.13 111.81,10.13 113,11.33 114.68,11.33 115.65,10.36 116.51,10.36 116.59,10.29 116.59,9.45 116.46,9.32 109.65,9.32 108.94,10.03 107.31,10.03 107.21,10.13 103.71,10.13 103.02,9.45 101.98,9.45 101.88,9.55 85.04,9.55 84.66,9.17 84.66,6.86 85.29,6.22 87.93,6.22 88.21,5.94 88.21,4.95 87.96,4.7
N3073888 on BOTTOM: 104.43,5.96 105.74,4.65 106.38,4.65 107.16,5.44 108.51,5.44 110.34,7.26 110.97,7.26 111.12,7.11 111.12,6.43 108.37,3.67 105.46,3.67 104.78,4.36 104.76,4.36 104.09,5.03 103.07,5.03 102.95,5.16 102.95,5.82 103.09,5.96
N3073903 on BOTTOM: 110.29,8.84 117.37,8.84 119.74,6.48 123.72,6.48 123.88,6.32 123.88,5.21 123.7,5.03 122.02,5.03 121.72,5.33 120.75,5.33 120.68,5.26 120.68,5.08 121.44,4.32 121.67,4.32 121.82,4.17 121.82,2.77 121.69,2.64 120.24,2.64 119.99,2.9 119.99,4.22 118.72,5.49 118.72,6.68 117.5,7.9 110.16,7.9 110.11,7.95 110.11,8.66
N3074477 on BOTTOM: 94.49,2.79 94.65,2.63 94.65,1.37 94.51,1.23 92.37,1.23 91.57,2.03 91.57,3.3 91.62,3.35 92.43,3.35 92.99,2.79
N3074493 on BOTTOM: 98.58,13.77 100.43,13.77 102.31,15.65 103.07,15.65 103.48,15.24 103.48,14.43 102.87,13.82 102.34,13.82 100.1,11.58 98.83,11.58 98.37,12.04 98.37,13.56
N3074930 on BOTTOM: 94.61,8.08 95.07,8.08 95.28,7.87 95.28,5.54 95.66,5.16 95.66,2.9 95.89,2.67 97.31,2.67 97.94,2.03 101.37,2.03 102.23,2.9 103.05,2.9 103.54,2.4 103.54,1.64 103.1,1.19 95.78,1.19 95.17,1.8 95.17,4.93 94.56,5.54 94.56,8.03
N3075106 on BOTTOM: 85.6,9.04 93.19,9.04 94.03,8.2 94.03,5.26 94.64,4.65 94.64,3.66 93.47,3.66 93.19,3.94 93.19,8.03 92.89,8.33 90.91,8.33 89.84,7.26 85.52,7.26 85.52,8.97
N3077075 on BOTTOM: 106.27,15.57 108.41,15.57 109.88,14.1 122.45,14.1 124.87,11.68 133.63,11.68 134.04,11.28 134.04,7.24 133.58,6.78 128.47,6.78 128.46,6.79 128.16,6.79 127.79,7.16 127.79,10.29 127.25,10.82 123.95,10.82 121.28,13.49 107.75,13.49 107.14,14.1 106.2,14.1 105.89,14.4 105.89,15.19
N3077081 on BOTTOM: 97.64,13.82 97.82,13.64 97.82,11.43 97.97,11.28 100.84,11.28 102.46,12.9 103.81,12.9 104.14,13.23 104.14,15.37 106.15,17.37 109.45,17.37 109.98,16.84 111.12,16.84 111.25,16.71 111.25,15.88 111.1,15.72 109.75,15.72 108.99,16.48 106.4,16.48 105.16,15.24 105.16,13.54 105.46,13.23 106.4,13.23 106.71,12.93 106.71,11.61 106.35,11.25 102.06,11.25 101.45,10.64 97.71,10.64 97.03,11.33 97.03,13.69 97.16,13.82
N3083007 on BOTTOM: 100.28,7.9 100.99,7.19 103.48,7.19 104.17,7.87 104.17,9.32 104.37,9.53 106.22,9.53 106.44,9.31 106.44,7.94 106.27,7.77 104.9,7.77 103.71,6.58 100.91,6.58 100.25,5.92 100.25,5.89 100.23,5.92 98.5,5.92 98.4,6.02 98.4,7.72 98.58,7.9
N3083089 on BOTTOM: 97.21,8.03 97.59,8.03 97.82,7.8 97.82,5.87 98.6,5.08 100.56,5.08 101.42,5.94 102.08,5.94 102.11,5.92 102.11,5.11 101.73,5.11 100.53,3.91 99.01,3.91 97.13,5.79 97.1,5.79 97.1,7.92
N3109029 on BOTTOM (solid shape): 8.51,21.11 7.19,20.62 8.51,20.04 7.19,19.56 3.66,19.56 3.66,21.69 7.16,21.69
N3109029 on BOTTOM: 3.91,23.85 3.91,17.14 4.78,16.28 6.22,16.28 6.58,15.93 6.58,13.79 6.27,13.49 4.75,13.49 3.68,12.42 3.68,9.58 3.34,9.23 1.65,9.23 1.24,9.64 1.24,23.93 1.57,24.26 3.51,24.26
N3109086 on BOTTOM (solid shape): 14.78,19.56 10.87,19.56 9.55,20.04 10.87,20.62 9.55,21.11 10.87,21.69 14.78,21.69
N3109086 on BOTTOM (solid shape): 16.21,23.62 16.21,22.23 14.05,22.23 14.05,23.57 14.66,24.94 15.14,23.62 15.72,24.94
N3109086 on BOTTOM: 13.07,13.45 11.86,13.45 11.42,13.89 11.42,15.98 11.86,16.42 13.17,16.42 13.92,17.17 13.92,17.2 14.05,17.32 14.05,22.76 14.35,23.06 16.21,23.06 16.21,22.25 17.02,21.44 17.02,10.59 20.42,7.19 20.42,2.44 19.81,1.83 15.04,1.83 14.43,2.44 14.43,12.09
N3119295 on BOTTOM: 63.42,35.81 64.62,35.81 67.31,33.12 69.88,33.12 69.88,33.13 70.37,33.63 70.37,34.76 67.77,37.36 63.83,37.36 63.42,36.96
N3151365 on BOTTOM: 98.22,22.48 100.63,22.48 101.14,21.97 101.14,20.83 100.63,20.32 98.15,20.32 97.71,20.75 97.71,21.97
N3168759 on BOTTOM: 48.62,5.16 48.44,4.98 47.73,4.98 47.52,5.18 47.52,9.07 48.67,10.21 52.45,10.21 53.04,9.63 53.06,9.63 53.06,8.94 52.55,8.43 49.02,8.43 48.62,8.03
N3178422 on BOTTOM: 94.61,15.98 95.55,15.98 95.68,15.85 95.68,14.86 95.35,14.53 95.35,11.63 95.2,11.48 94.61,11.48 94.51,11.58 94.51,15.88
N3201252 on BOTTOM: 113.51,6.22 114.81,6.22 116.81,4.22 116.81,2.64 116.71,2.54 115.56,2.54 115.39,2.72 115.39,2.98 114.48,3.89 113.31,3.89 112.24,2.82 111.28,2.82 111.05,3.05 111.05,3.76
N3203116 on BOTTOM: 129.78,15.79 129.26,15.27 126.85,15.27 122.82,19.29 120.54,19.29 120.37,19.46 120.37,20.65 120.36,20.66 120.56,20.87 122.9,20.87 123.34,21.31 123.34,25.3 126.8,28.75 129.41,28.75 129.78,28.38
N3205512 on BOTTOM: 122.38,18.69 126.82,14.25 136.32,14.25 136.93,13.64 136.93,1.32 135.81,0.2 114.48,0.2 113.21,1.47 113.21,2.74 113.36,2.9 114.5,2.9 114.63,2.77 114.63,1.07 115.01,0.69 134.67,0.69 136.22,2.24 136.22,12.73 135.23,13.72 126.24,13.72 123.62,16.33 118.08,16.33 117.75,16.66 117.75,18.52 117.93,18.69
N3220537 on BOTTOM: 87.2,10.62 85.75,10.62 85.37,11 85.37,14.2 86.3,15.13 87.21,15.13 87.43,14.91 87.43,13.79 87.27,13.64 87.27,10.69
N3225688 on BOTTOM: 107.37,6.07 105.54,6.07 105.23,6.38 105.23,6.93 105.38,7.09 106.45,7.09 106.45,7.11 107.54,8.2 108.53,8.2 108.66,8.08 108.66,7.37
N3249281 on BOTTOM: 61.3,12.81 60.96,13.16 60.96,14.68 60.63,15.01 59.69,15.01 59.27,14.59 59.27,11.26 59.74,10.79 60.78,10.79 61.3,11.32
N3253476 on BOTTOM: 90.93,0.81 109.68,0.81 110.87,2.01 112.12,2.01 112.34,1.78 112.34,0.64 111.91,0.2 90.27,0.2 89.41,1.07 89.41,2.39 89.51,2.49 90.27,2.49 90.35,2.41 90.35,1.4
N3273823 on BOTTOM: 37.49,5.99 37.49,4.72 37.19,4.42 37.19,3.02 36.58,3.02 36.09,3.51 36.09,5.64 36.45,5.99
N3286857 on BOTTOM: 91.31,35.71 95.35,35.71 95.4,35.66 95.4,34.37 94.41,33.38 94.41,31.24 94.36,31.19 92.91,31.19 91.19,32.92 91.19,35.59

Small or netless copper shapes (teardrops, artwork), in the pictures only: 1 on BOTTOM

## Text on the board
Ref Des/Silkscreen Top: TM | JP1 | JP3 | HS2 | JP2 | S/N | LYTSwitch- 4 | DER 442 | REV A | 1441 | LED | DIM | - | +
PAGE_OUTLINE: SLOT 1
PEN17: PLEASE DELETE THESE VIAS: | 13   MATERIAL FR4 COPPER 2oz THICKNESS 0.062"
User.5: FIGURE | SIZE | 30.0 | 35.0 | 38.0 | 40.0 | 46.0 | 50.0 | 52.0 | 55.0 | 60.0 | 70.0 | DRILL CHART: TOP to BOTTOM | ALL UNITS ARE IN MILS | QTY | 30 | 6 | 1 | 36 | 2 | 10 | 5
